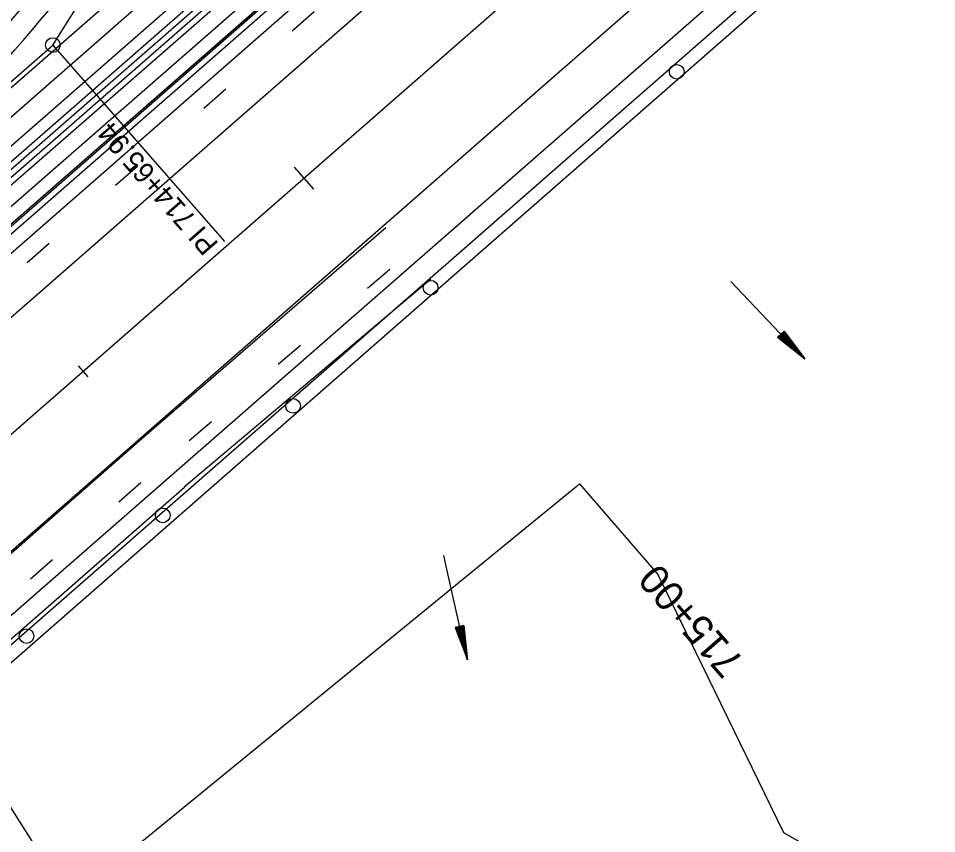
# Model space of a CAD drawing. Extents: x 1300404 to 1323571, y 234004 to 252077.
# Drawn here: x 1310212.2 to 1310525.4, y 240359 to 240637.1 of the extents above; entities that cross this region are included whole.
import ezdxf

# ---------------------------------------------------------------- set-up
doc = ezdxf.new("R2010")
doc.units = 0
for name, color, linetype in [('R_Barrel', 7, 'Continuous'), ('R_Barrier Wall', 7, 'Continuous'), ('R_Const Limits', 7, 'Continuous'), ('R_Draft', 7, 'Continuous'), ('R_Flooplain', 7, 'Continuous'), ('R_Flow Arrows', 7, 'Continuous'), ('R_Horz Alg Annot', 7, 'Continuous'), ('R_Horz Alg Annot Leader', 7, 'Continuous'), ('R_Horz Alg Major Ticks', 7, 'Continuous'), ('R_Horz Alg Minor Ticks', 7, 'Continuous'), ('R_Horz Alg Station Annot', 7, 'Continuous'), ('R_Horz Alg Tangents', 7, 'Continuous'), ('R_Lane Edge', 7, 'Continuous'), ('R_Proposed', 7, 'Continuous'), ('R_Shoulder', 7, 'Continuous'), ('R_Temp Barrier Wall', 7, 'Continuous'), ('R_Temp Travel Lane', 7, 'Continuous'), ('R_Temp Travel Stripe', 7, 'Continuous')]:
    doc.layers.add(name, color=color, linetype=linetype)

msp = doc.modelspace()

# ---------------------------------------------------------------- linework, layer by layer
at = {"layer": 'R_Barrel'}
for centre in [(1310436.76, 240618.83), (1310352.85, 240545.21), (1310305.91, 240504.89), (1310261.46, 240467.55), (1310215.02, 240426.38)]:
    msp.add_circle(centre, 2.5, dxfattribs=at)
at = {"layer": 'R_Barrier Wall'}
for p, q in [((1309593.62, 240046.84), (1310923.44, 241209.65)), ((1309594.93, 240045.34), (1310924.76, 241208.15))]:
    msp.add_line(p, q, dxfattribs=at)
at = {"layer": 'R_Const Limits'}
msp.add_lwpolyline([(1310208.13, 240370.38), (1310208.13, 240370.38), (1310208.13, 240370.38), (1310208.13, 240370.38), (1310208.13, 240370.38), (1310208.13, 240370.38), (1310233, 240330.85), (1310233, 240330.85), (1310241.64, 240325.82), (1310250.22, 240320.68), (1310258.75, 240315.45), (1310267.27, 240310.23), (1310275.8, 240305), (1310284.33, 240299.77), (1310292.84, 240294.52), (1310301.4, 240289.36), (1310309.98, 240284.23), (1310318.58, 240279.12), (1310327.17, 240274), (1310327.17, 240274), (1310327.17, 240274), (1310327.17, 240274), (1310327.17, 240274)], dxfattribs=at)
at = {"layer": 'R_Draft'}
for p, q in [((1308396.96, 238971.92), (1312368.36, 242444.53)), ((1308407.83, 238959.5), (1312379.22, 242432.11)), ((1308447.32, 238914.33), (1312418.71, 242386.94)), ((1308458.18, 238901.91), (1312429.57, 242374.52)), ((1309184.47, 239689.08), (1312131.36, 242265.86)), ((1309037.78, 239548.19), (1312137.61, 242258.71)), ((1309193.69, 239678.54), (1312140.58, 242255.32)), ((1309413.86, 239721.62), (1312065.67, 242040.38)), ((1309410.89, 239725), (1311987.97, 241978.41)), ((1309410.89, 239725), (1311987.97, 241978.41))]:
    msp.add_line(p, q, dxfattribs=at)
at = {"layer": 'R_Flooplain'}
for p, q in [((1310180.38, 240295.99), (1310403.59, 240478.31)), ((1310403.59, 240478.31), (1310430.47, 240447.32)), ((1310473.27, 240359.27), (1310430.47, 240447.32)), ((1310628.59, 240271.59), (1310473.27, 240359.27))]:
    msp.add_line(p, q, dxfattribs=at)
at = {"layer": 'R_Flow Arrows'}
for p, q in [((1310473.37, 240530.39), (1310471.18, 240528.28)), ((1310473.37, 240530.39), (1310480.44, 240520.89)), ((1310471.18, 240528.28), (1310480.44, 240520.89)), ((1310364.15, 240430.05), (1310361.19, 240429.36)), ((1310361.19, 240429.36), (1310365.37, 240418.27)), ((1310364.15, 240430.05), (1310365.37, 240418.27))]:
    msp.add_line(p, q, dxfattribs=at)
for points in [[(1310455.23, 240547.28), (1310459.21, 240543.1), (1310480.33, 240520.78)], [(1310471.83, 240528.91), (1310476.15, 240524.44), (1310476.73, 240523.84)], [(1310472.05, 240529.12), (1310476.37, 240524.65), (1310478.58, 240522.36)], [(1310472.49, 240529.55), (1310476.81, 240525.08), (1310479.02, 240522.78)], [(1310472.71, 240529.76), (1310477.03, 240525.29), (1310477.61, 240524.69)], [(1310472.93, 240529.97), (1310476.19, 240526.59)], [(1310473.15, 240530.18), (1310474.78, 240528.49)], [(1310471.4, 240528.49), (1310473.03, 240526.8)], [(1310471.62, 240528.7), (1310474.88, 240525.32)], [(1310357.2, 240453.83), (1310358.48, 240448.21), (1310365.23, 240418.24)], [(1310361.49, 240429.43), (1310362.03, 240427.14)], [(1310361.78, 240429.5), (1310362.86, 240424.92)], [(1310362.08, 240429.56), (1310363.51, 240423.51), (1310363.7, 240422.7)], [(1310362.38, 240429.63), (1310363.8, 240423.58), (1310364.53, 240420.49)], [(1310362.97, 240429.77), (1310364.4, 240423.72), (1310365.12, 240420.62)], [(1310363.26, 240429.85), (1310364.69, 240423.79), (1310364.88, 240422.98)], [(1310363.56, 240429.91), (1310364.64, 240425.34)], [(1310363.86, 240429.98), (1310364.4, 240427.7)]]:
    msp.add_lwpolyline(points, dxfattribs=at)
at = {"layer": 'R_Horz Alg Annot Leader'}
msp.add_lwpolyline([(1310224.01, 240627.95), (1310282.59, 240560.96)], dxfattribs=at)
msp.add_lwpolyline([(1310224.01, 240627.95), (1310282.59, 240560.96)], dxfattribs=at)
at = {"layer": 'R_Horz Alg Major Ticks'}
msp.add_lwpolyline([(1310306.28, 240586.31), (1310312.86, 240578.78)], dxfattribs=at)
msp.add_lwpolyline([(1310306.28, 240586.31), (1310312.86, 240578.78)], dxfattribs=at)
at = {"layer": 'R_Horz Alg Minor Ticks'}
msp.add_lwpolyline([(1310232.64, 240518.6), (1310235.93, 240514.83)], dxfattribs=at)
msp.add_lwpolyline([(1310232.64, 240518.6), (1310235.93, 240514.83)], dxfattribs=at)
at = {"layer": 'R_Horz Alg Tangents'}
for p, q in [((1310224.01, 240627.95), (1310343.05, 240817.02)), ((1310224.01, 240627.95), (1310343.05, 240817.02)), ((1310055.82, 240480.88), (1310224.01, 240627.95)), ((1310055.82, 240480.88), (1310224.01, 240627.95))]:
    msp.add_line(p, q, dxfattribs=at)
at = {"layer": 'R_Lane Edge'}
for p, q in [((1309254.07, 239731.34), (1311026.82, 241281.45)), ((1309254.07, 239731.34), (1311026.82, 241281.45)), ((1310188.6, 240594.99), (1310884.73, 241203.69)), ((1309589.67, 240051.36), (1310894.61, 241192.4))]:
    msp.add_line(p, q, dxfattribs=at)
for radius, start in [(1520.39, 311.16667), (1535.39, 317.70521)]:
    msp.add_arc((1309050.08, 241631.07), radius, start, 327.80537, dxfattribs=at)
at = {"layer": 'R_Proposed'}
for p, q in [((1308427.57, 238936.91), (1312793.8, 242754.77)), ((1308427.57, 238936.91), (1312793.8, 242754.77)), ((1309180.37, 239595.16), (1312398.96, 242409.52)), ((1309180.37, 239595.16), (1312398.96, 242409.52)), ((1309584.71, 240056.98), (1310889.67, 241198.05)), ((1309584.71, 240056.98), (1310889.67, 241198.05))]:
    msp.add_line(p, q, dxfattribs=at)
msp.add_circle((1310224.01, 240627.95), 2.5, dxfattribs=at)
msp.add_circle((1310224.01, 240627.95), 2.5, dxfattribs=at)
msp.add_arc((1309050.08, 241631.07), 1527.89, 311.16667, 327.80537, dxfattribs=at)
msp.add_arc((1309050.08, 241631.07), 1527.89, 311.16667, 327.80537, dxfattribs=at)
msp.add_arc((1309050.08, 241631.07), 1527.89, 311.16667, 327.80537, dxfattribs=at)
msp.add_arc((1309050.08, 241631.07), 1527.89, 311.16667, 327.80537, dxfattribs=at)
at = {"layer": 'R_Shoulder'}
for p, q in [((1309482.39, 239944.26), (1311020.24, 241288.97)), ((1309482.39, 239944.26), (1311020.24, 241288.97)), ((1309592.3, 240048.35), (1310897.24, 241189.39))]:
    msp.add_line(p, q, dxfattribs=at)
msp.add_arc((1309050.08, 241631.07), 1514.39, 311.16667, 327.80537, dxfattribs=at)
at = {"layer": 'R_Temp Barrier Wall'}
for points in [[(1311027.31, 241280.88), (1310559.74, 240872.07), (1309471.94, 239921.22), (1308468.86, 239041.61)], [(1311028.63, 241279.38), (1310561.08, 240870.59), (1309473.28, 239919.73), (1308470.17, 239040.11)]]:
    msp.add_lwpolyline(points, dxfattribs=at)
at = {"layer": 'R_Temp Travel Lane'}
for p, q in [((1310254.39, 240493.73), (1310337.53, 240565.75)), ((1310268.81, 240477.24), (1310352.9, 240548.18)), ((1309953.25, 240230.44), (1310254.39, 240493.73)), ((1309139.54, 239489.78), (1310268.87, 240477.17))]:
    msp.add_line(p, q, dxfattribs=at)
at = {"layer": 'R_Temp Travel Stripe'}
for p, q in [((1310313.13, 240639.24), (1310305.6, 240632.66)), ((1310283.01, 240612.91), (1310275.48, 240606.33)), ((1310252.89, 240586.59), (1310245.36, 240580.01)), ((1310222.78, 240560.27), (1310215.25, 240553.68)), ((1310331.29, 240545.06), (1310338.9, 240551.55)), ((1310300.88, 240519.08), (1310308.48, 240525.57)), ((1310270.46, 240493.1), (1310278.07, 240499.59)), ((1310246.49, 240472.22), (1310254.02, 240478.8)), ((1310216.38, 240445.89), (1310223.91, 240452.47))]:
    msp.add_line(p, q, dxfattribs=at)

# ---------------------------------------------------------------- texts
at = {"layer": 'R_Horz Alg Annot'}
msp.add_text('PI 714+65.94', height=7, rotation=131.1667, dxfattribs=at).set_placement((1310280.8, 240560.21))
msp.add_text('PI 714+65.94', height=7, rotation=131.1667, dxfattribs=at).set_placement((1310280.8, 240560.21))
at = {"layer": 'R_Horz Alg Station Annot'}
msp.add_text('715+00', height=10, rotation=131.1667, dxfattribs=at).set_placement((1310460.18, 240417.89))
msp.add_text('715+00', height=10, rotation=131.1667, dxfattribs=at).set_placement((1310460.18, 240417.89))

doc.saveas('drawing.dxf')
